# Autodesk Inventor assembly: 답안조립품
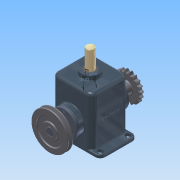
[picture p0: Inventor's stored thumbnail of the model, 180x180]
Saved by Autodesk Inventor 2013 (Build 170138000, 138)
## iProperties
Created: 2015-03
Part Number: 답안조립품
Document SubType Name: Assembly
Designer: Administrator
Mass: 8579.28 g
Surface Area: 4386.42 cm^2
Volume: 1982.54 cm^3
Density: 4.32742 g/cm^3
Author: Administrator
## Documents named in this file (15)
- C:\Documents and Settings\Administrator\바탕 화면\350305V1028\답안조립품.iam
- C:\Documents and Settings\Administrator\바탕 화면\350305V1028\본체.ipt
- C:\Documents and Settings\Administrator\바탕 화면\350305V1028\베어링 6205.ipt
- C:\Documents and Settings\Administrator\바탕 화면\350305V1028\V-벨트풀리.ipt
- C:\Documents and Settings\Administrator\바탕 화면\350305V1028\멈춤링.ipt
- C:\Documents and Settings\Administrator\바탕 화면\350305V1028\오일실.ipt
- C:\Documents and Settings\Administrator\바탕 화면\350305V1028\커버.ipt
- C:\Documents and Settings\Administrator\바탕 화면\350305V1028\키 8x8.ipt
- C:\Documents and Settings\Administrator\바탕 화면\350305V1028\편심축.ipt
- C:\Documents and Settings\Administrator\바탕 화면\350305V1028\M4x0.5.ipt
- C:\Documents and Settings\Administrator\바탕 화면\350305V1028\체인 스프로킷.ipt
- C:\Documents and Settings\Administrator\바탕 화면\350305V1028\부시.ipt
- C:\Documents and Settings\Administrator\바탕 화면\350305V1028\멈춤나사 M5x0.5.ipt
- C:\Documents and Settings\Administrator\바탕 화면\350305V1028\슬라이드.ipt
- C:\Documents and Settings\Administrator\바탕 화면\350305V1028\가변스프링.ipt
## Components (9 placed, 4 different names)
1. V-벨트풀리:1 — 플러쉬:4, 각도:3
2. 5-체인 스프로킷:1 — 플러쉬:5, 각도:4
3. 가변스프링:1
4. M4x0.5:1
5. M4x0.5:2
6. M4x0.5:3
7. M4x0.5:4
8. M4x0.5:5
9. M4x0.5:6
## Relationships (4: Flush 2, Angle 2)
- 플러쉬:4 [Flush]: V-벨트풀리:1
- 각도:3 [Angle]: V-벨트풀리:1
- 플러쉬:5 [Flush]: 5-체인 스프로킷:1
- 각도:4 [Angle]: 5-체인 스프로킷:1
